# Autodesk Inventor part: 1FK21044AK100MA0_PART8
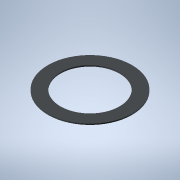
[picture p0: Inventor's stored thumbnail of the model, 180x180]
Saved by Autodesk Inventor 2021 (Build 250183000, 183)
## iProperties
Created: 2025-04
Part Number: 1FK21044AK100MA0_PART8
Material: Generic
Catalog Web Link: www.3dfindit.com
Description: -Servo synchronous motor
Document SubType Name: Modeling
Designer: psAdmin
Mass: 0.27214 g
Surface Area: 11.8752 cm^2
Volume: 0.27214 cm^3
Density: 1 g/cm^3
Appearance: PSOLRGB-212-217-219
Category: PARTsolutions
Title: 1FK21044AK100MA0_PART8
Author: Cadenas PARTsolutions
Comments: Servo synchronous motor
Sending System: PARTsolutions
Preprocessor: ST-DEVELOPER v19.3
PSOL_IDENT_0: {$CADENAS_DATA/23d-libs/siemens_ag/_cat_/5e/d8/1fk21044ak100ma0.prj},213 {VTYP=3D},{NB=1FK21044AK100
PSOL_IDENT_1: MA0_PART8},{LINA=1FK21044AK100MA0_PART8},{NN=1FK21044AK100MA0_PART8},{NOPRJ=TRUE},{DATE=19.08.2025 1
PSOL_IDENT_2: 4:00:41},{GEOMDATE=30.07.2025 02:00:53},{VERSION=},{LINEID=10},{WBVAR=},{WBNUMERIC=}  {NB=1FK21044AK
PSOL_IDENT_3: 100MA0_PART8},{LINA=1FK21044AK100MA0_PART8},{KT=DUMMY},{PREVIEW=../../../_pool_/cb/72/p_d211_xx_0043
PSOL_IDENT_4: 4j.png},{DESCSHORT=SIMOTICS S-1FK2 HD, SINAMICS S210 3AC 400V-480V, 0.95 Nm, 6000 rpm},{DESCLONG=SIM
PSOL_IDENT_5: OTICS S-1FK2 HD servo motor M0=1.27 Nm; PN = 0.6 kW at nN=6000 rpm (380-480 V); PN = 0.4 kW at nN=30
PSOL_IDENT_6: 00 rpm (200-240 V); with holding brake; degree of protection IP64; cylindrical shaft D19x40mm; absol
PSOL_IDENT_7: ute encoder 22-bit + 12-bit multiturn (encoder AM22DQC); with OCC interface; plug size M17, rotatabl
PSOL_IDENT_8: e; SIMOTICS S-1FK2 servomotorfor a wide range of uses in industrial environments. SIMOTICS S‑1FK2 se
PSOL_IDENT_9: rvomotors are compact synchronous motors with a high dynamic performance that set themselves apart a
PSOL_IDENT_10: s a result of their high power density, degree of protection and overload capability. The motors are
PSOL_IDENT_11: available in two variants: as High Dynamic variant (highest dynamic performance as a result of the
PSOL_IDENT_12: low intrinsic moment of inertia for applications demanding a high dynamic performance with low moved
PSOL_IDENT_13: masses) - and as Compact variant (precise and stable closed-loop control for medium up to large mov
PSOL_IDENT_14: ed masses as a result of a medium intrinsic moment of inertia). SIMOTICSS‑1FK2 servomotors fully exp
PSOL_IDENT_15: loit their strengths in a system with the SINAMICSS210 frequency converter and simple connection usi
PSOL_IDENT_16: ng the one cable connection (OCC). Advantages include the short control and positioning times, fast
PSOL_IDENT_17: and precise correction of disturbing quantities as well as stable control with a high dynamic perfor
PSOL_IDENT_18: mance. The servo motors can be configured to address a wide range of requirements. For example with
PSOL_IDENT_19: and without holding brake, IP64 or IP65 degree of protection, singleturn or multiturn absolute encod
PSOL_IDENT_20: ers - to name just a few. Further, the servomotors are available in different shaft heights extendin
PSOL_IDENT_21: g from 20 to 100. A shaft sealing ring is available to achieve an IP65 degree of protection and for
PSOL_IDENT_22: subsequent mounting at the motor or as spare part. SIMOTICS - the optimum motor for each and every m
PSOL_IDENT_23: otion control application.},{INTNO=804766910005},{SUPPLIERALTNO=1FK2104-4AK10-0MA0},{MANUID=1FK21044
PSOL_IDENT_24: AK100MA0},{MANUNAME=Siemens},{MANUTYPEDESC=Synchronous motor 1FK2-HD 1,27 Nm},{AAU732=SIMOTICS},{AAO
PSOL_IDENT_25: 057=S-1FK2},{AAU734=SIMOTICS S-1FK2 HD servo motor M0=1.27 Nm; PN = 0.6 kW at nN=6000 rpm (380-480 V
PSOL_IDENT_26: ); PN = 0.4 kW at nN=3000 rpm (200-240 V); with holding brake; degree of protection IP64; cylindrica
PSOL_IDENT_27: l shaft D19x40mm; absolute encoder 22-bit + 12-bit multiturn (encoder AM22DQC); with OCC interface;
PSOL_IDENT_28: plug size M17, rotatable;},{AAW338=Synchronous motor 1FK2-HD 1,27 Nm},{AAO742=SIMOTICS},{AAO663=4042
PSOL_IDENT_29: 948691076},{NOCUPEROU=1},{PRICEQUANTITY=1},{QUANTITYMIN=1},{QUANTITYINT=1},{CTN=85015100},{COO=DE},{
PSOL_IDENT_30: AAO676=1FK2104-4AK10-0MA0},{AAO677=Siemens AG},{ORDERUNIT=C62},{CONTENTUNIT=C62}
NB: 1FK21044AK100MA0_PART8
NT: Servo synchronous motor
NBSYN: $MANUID._PART8
LINA: 1FK21044AK100MA0_PART8
CATALOG: SIEMENS
PREVIEW: ../../../_pool_/cb/72/p_d211_xx_00434j.png
DESCSHORT: SIMOTICS S-1FK2 HD, SINAMICS S210 3AC 400V-480V, 0.95 Nm, 6000 rpm
DESCLONG: SIMOTICS S-1FK2 HD servo motor M0=1.27 Nm; PN = 0.6 kW at nN=6000 rpm (380-480 V); PN = 0.4 kW at nN=3000 rpm (200-240 V); with holding brake; degree of protect
INTNO: 804766910005
SUPPLIERALTNO: 1FK2104-4AK10-0MA0
MANUID: 1FK21044AK100MA0
MANUNAME: Siemens
MANUTYPEDESC: Synchronous motor 1FK2-HD 1,27 Nm
AAU732: SIMOTICS
AAO057: S-1FK2
AAU734: SIMOTICS S-1FK2 HD servo motor M0=1.27 Nm; PN = 0.6 kW at nN=6000 rpm (380-480 V); PN = 0.4 kW at nN=3000 rpm (200-240 V); with holding brake; degree of protect
AAW338: Synchronous motor 1FK2-HD 1,27 Nm
AAO742: SIMOTICS
AAO663: 4042948691076.0
NOCUPEROU: 1
PRICEQUANTITY: 1
QUANTITYMIN: 1
QUANTITYINT: 1
CTN: 85015100
COO: DE
ARTICLENO: 1FK21044AK100MA0_PART8
BOMINFO: 1FK21044AK100MA0_PART8
CREATOR: CADENAS GmbH
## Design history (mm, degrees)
feature "2025_04_17_15_35_41_0968"
body "Solid1"
